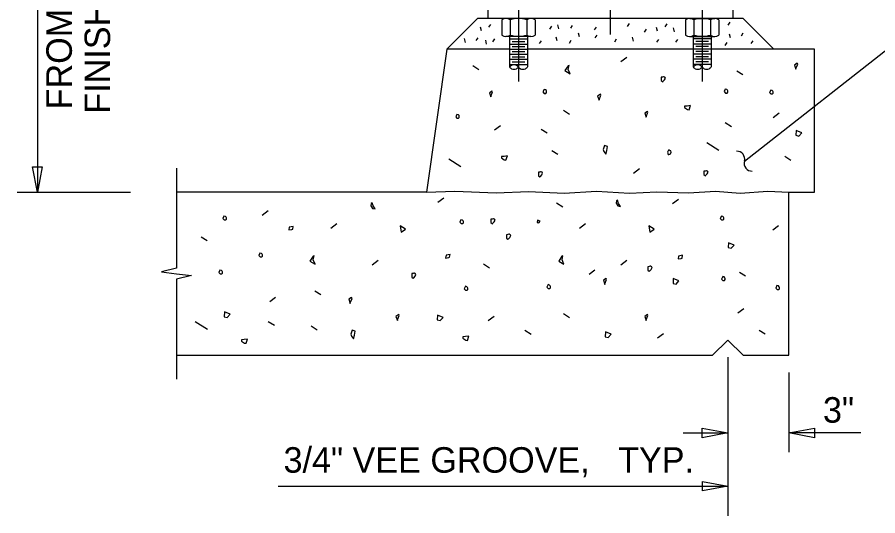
# Model space of a CAD drawing. Extents: x 0 to 22.7, y 0 to 15.7.
# Drawn here: x 16.522 to 20.034, y 3.448 to 5.483 of the extents above; entities that cross this region are included whole.
import ezdxf

# ---------------------------------------------------------------- set-up
doc = ezdxf.new("R2010")
doc.units = 0
for name, color, linetype in [('BRDG_ANNO_General-Notes', 7, 'Continuous'), ('BRDG_BASE_Dtlctrln', 7, 'Continuous'), ('BRDG_BASE_Obj-Line', 7, 'Continuous'), ('BRDG_BASE_Pattern', 7, 'Continuous'), ('BRDG_BASE_Phtline', 7, 'Continuous'), ('Default', 7, 'Continuous')]:
    doc.layers.add(name, color=color, linetype=linetype)

# ---------------------------------------------------------------- blocks, each defined once
blk = doc.blocks.new('TERM')
at = {"layer": 'Default'}
for p, q in [((-1.6, -0.267), (-1.6, 0.267)), ((-1.6, 0.267), (0, 0)), ((0, 0), (-1.6, -0.267))]:
    blk.add_line(p, q, dxfattribs=at)

msp = doc.modelspace()

# ---------------------------------------------------------------- linework, layer by layer
at = {"layer": 'BRDG_ANNO_General-Notes'}
for p, q in [((16.6043, 6.5193), (16.6043, 4.7693)), ((16.5849, 4.8726), (16.6236, 4.8726)), ((16.6043, 4.7693), (16.5849, 4.8726)), ((16.6236, 4.8726), (16.6043, 4.7693)), ((16.5219, 4.7693), (16.9841, 4.7693)), ((19.6716, 4.0332), (19.6716, 3.7074)), ((19.2393, 3.7856), (19.4216, 3.7856)), ((19.9648, 3.7856), (19.6716, 3.7856)), ((19.3182, 3.5489), (19.3182, 3.5877)), ((19.3182, 3.5877), (19.4216, 3.5683)), ((17.5869, 3.5683), (19.4216, 3.5683)), ((19.4216, 3.5683), (19.3182, 3.5489))]:
    msp.add_line(p, q, dxfattribs=at)
msp.add_lwpolyline([(19.4896, 4.8953), (20.1276, 5.3956), (20.5327, 5.3956)], dxfattribs=at)
for centre, start, end in [((19.4585, 4.9036), 344.9792, 91.2394), ((19.5208, 4.8869), 164.9792, 271.2394)]:
    msp.add_arc(centre, 0.0323, start, end, dxfattribs=at)
at = {"layer": 'BRDG_BASE_Dtlctrln'}
for p, q in [((18.9424, 7.3563), (18.9424, 5.4121)), ((18.5674, 5.7676), (18.5674, 5.2206)), ((19.3174, 5.7676), (19.3174, 5.2206)), ((19.4216, 4.0957), (19.4216, 3.4476))]:
    msp.add_line(p, q, dxfattribs=at)
at = {"layer": 'BRDG_BASE_Obj-Line'}
for p, q in [((18.4424, 5.5609), (18.4424, 5.4776)), ((19.4424, 5.5609), (19.4424, 5.4776)), ((18.2757, 5.3526), (18.4007, 5.4776)), ((19.4841, 5.4776), (18.4007, 5.4776)), ((18.4991, 5.4722), (18.4991, 5.4101)), ((18.5674, 5.4776), (18.5166, 5.4776)), ((18.5332, 5.4722), (18.5332, 5.4101)), ((18.6183, 5.4776), (18.5674, 5.4776)), ((18.6016, 5.4722), (18.6016, 5.4101)), ((18.6358, 5.4722), (18.6358, 5.4101)), ((19.2491, 5.4722), (19.2491, 5.4101)), ((19.2666, 5.4776), (19.3174, 5.4776)), ((19.2832, 5.4722), (19.2832, 5.4101)), ((19.3174, 5.4776), (19.3683, 5.4776)), ((19.3516, 5.4722), (19.3516, 5.4101)), ((19.3858, 5.4722), (19.3858, 5.4101)), ((19.6091, 5.3526), (19.4841, 5.4776)), ((18.5674, 5.4047), (18.5166, 5.4047)), ((18.5309, 5.4047), (18.5309, 5.2797)), ((18.5309, 5.3943), (18.6039, 5.3943)), ((18.5309, 5.3734), (18.6039, 5.3734)), ((18.5414, 5.3839), (18.5934, 5.3839)), ((18.6183, 5.4047), (18.5674, 5.4047)), ((18.6039, 5.4047), (18.6039, 5.2797)), ((19.2666, 5.4047), (19.3174, 5.4047)), ((19.2809, 5.4047), (19.2809, 5.2797)), ((19.3539, 5.3943), (19.2809, 5.3943)), ((19.3539, 5.3734), (19.2809, 5.3734)), ((19.3434, 5.4047), (19.2914, 5.4047)), ((19.3434, 5.3839), (19.2914, 5.3839)), ((19.3174, 5.4047), (19.3683, 5.4047)), ((19.3539, 5.4047), (19.3539, 5.2797)), ((18.2757, 5.3526), (18.1924, 4.7693)), ((18.5309, 5.3526), (18.2757, 5.3526)), ((18.5309, 5.3526), (18.6039, 5.3526)), ((18.5414, 5.363), (18.5934, 5.363)), ((18.5414, 5.3422), (18.5934, 5.3422)), ((19.2809, 5.3526), (18.6039, 5.3526)), ((19.3539, 5.3526), (19.2809, 5.3526)), ((19.3434, 5.363), (19.2914, 5.363)), ((19.3434, 5.3422), (19.2914, 5.3422)), ((19.7757, 5.3526), (19.3539, 5.3526)), ((19.7757, 4.7693), (19.7757, 5.3526)), ((18.5309, 5.3318), (18.6039, 5.3318)), ((18.5309, 5.3109), (18.6039, 5.3109)), ((18.5414, 5.3214), (18.5934, 5.3214)), ((19.3539, 5.3318), (19.2809, 5.3318)), ((19.3539, 5.3109), (19.2809, 5.3109)), ((19.3434, 5.3214), (19.2914, 5.3214)), ((18.5309, 5.2901), (18.6039, 5.2901)), ((18.5414, 5.3005), (18.5934, 5.3005)), ((19.3539, 5.2901), (19.2809, 5.2901)), ((19.3434, 5.3005), (19.2914, 5.3005)), ((18.1924, 4.7693), (17.1716, 4.7693)), ((19.6716, 4.1026), (19.6716, 4.7693)), ((19.6716, 4.7693), (19.7757, 4.7693)), ((19.4216, 4.1651), (19.3591, 4.1026)), ((19.4216, 4.1651), (19.4841, 4.1026)), ((17.1716, 4.1026), (19.3591, 4.1026)), ((19.4841, 4.1026), (19.6716, 4.1026))]:
    msp.add_line(p, q, dxfattribs=at)
for points in [[(17.1716, 4.8665), (17.1716, 4.459), (17.1101, 4.4436), (17.1716, 4.4359), (17.2331, 4.4282), (17.1716, 4.4129), (17.1716, 4.0054)], [(18.1924, 4.7693), (18.3085, 4.7726), (18.4759, 4.7658), (18.6081, 4.7713), (18.7539, 4.7651), (18.8861, 4.7732), (19.0211, 4.7651), (19.1318, 4.7705), (19.2614, 4.7665), (19.372, 4.7726), (19.4719, 4.7645), (19.5853, 4.7726), (19.6716, 4.7693)]]:
    msp.add_lwpolyline(points, dxfattribs=at)
for centre, radius, start, end in [((18.5161, 5.448), 0.0296, 54.7697, 125.2303), ((18.5674, 5.3672), 0.1104, 71.9685, 108.0315), ((18.6187, 5.448), 0.0296, 54.7697, 125.2303), ((19.2661, 5.448), 0.0296, 54.7697, 125.2303), ((19.3174, 5.3672), 0.1104, 71.9685, 108.0316), ((19.3687, 5.448), 0.0296, 54.7697, 125.2303), ((18.5161, 5.4343), 0.0296, 234.7697, 305.2303), ((18.5674, 5.5151), 0.1104, 251.9685, 288.0316), ((18.6187, 5.4343), 0.0296, 234.7697, 305.2303), ((19.2661, 5.4343), 0.0296, 234.7697, 305.2303), ((19.3174, 5.5151), 0.1104, 251.9684, 288.0315), ((19.3687, 5.4343), 0.0296, 234.7697, 305.2303), ((18.5492, 5.2658), 0.0228, 36.8699, 143.1301), ((18.5492, 5.2931), 0.0228, 216.8699, 323.1301), ((18.5856, 5.2931), 0.0228, 216.8699, 323.1301), ((19.2992, 5.2658), 0.0228, 36.8699, 143.1301), ((19.2992, 5.2931), 0.0228, 216.8699, 323.1301), ((19.3356, 5.2931), 0.0228, 216.8699, 323.1301)]:
    msp.add_arc(centre, radius, start, end, dxfattribs=at)
at = {"layer": 'BRDG_BASE_Pattern'}
for p, q in [((19.0098, 5.319), (18.9857, 5.3007)), ((18.3812, 5.2854), (18.4059, 5.2698)), ((19.4589, 5.2646), (19.4836, 5.249)), ((18.7517, 5.1027), (18.7764, 5.0871)), ((19.6311, 5.0908), (19.607, 5.0724)), ((18.494, 5.0396), (18.4699, 5.0213)), ((18.66, 5.026), (18.6848, 5.0104)), ((19.4117, 5.0526), (19.4365, 5.0369)), ((19.336, 4.9711), (19.3855, 4.9398)), ((18.7033, 4.939), (18.728, 4.9233)), ((18.2828, 4.9042), (18.3323, 4.8729)), ((19.6544, 4.9152), (19.6791, 4.8995)), ((19.0611, 4.8633), (19.037, 4.845)), ((17.1716, 4.7693), (17.1716, 4.7693)), ((18.2624, 4.7447), (18.2384, 4.7264)), ((18.7232, 4.7247), (18.748, 4.7091)), ((19.2203, 4.7387), (19.1962, 4.7204)), ((17.5454, 4.692), (17.5214, 4.6738)), ((17.8262, 4.639), (17.8021, 4.6207)), ((18.8412, 4.639), (18.8172, 4.6207)), ((19.6291, 4.6317), (19.6051, 4.6134)), ((17.2724, 4.5869), (17.2972, 4.5713)), ((17.9947, 4.4895), (17.9707, 4.4712)), ((18.425, 4.4759), (18.4497, 4.4603)), ((19.0098, 4.4895), (18.9857, 4.4712)), ((18.8797, 4.4508), (18.8556, 4.4325)), ((19.4695, 4.4427), (19.4943, 4.4271)), ((17.7366, 4.3662), (17.7613, 4.3507)), ((17.5765, 4.3393), (17.5524, 4.321)), ((19.4871, 4.2929), (19.4631, 4.2746)), ((18.4685, 4.2612), (18.4445, 4.243)), ((18.7517, 4.2732), (18.7764, 4.2577)), ((17.2488, 4.2412), (17.2983, 4.2099)), ((17.5466, 4.2411), (17.5714, 4.2255)), ((17.7215, 4.2224), (17.7461, 4.2067)), ((18.5941, 4.2048), (18.6189, 4.1892)), ((19.1594, 4.191), (19.1354, 4.1728)), ((19.5497, 4.2059), (19.5745, 4.1903))]:
    msp.add_line(p, q, dxfattribs=at)
for points in [[(18.7698, 5.284), (18.757, 5.2647), (18.7786, 5.2517), (18.7707, 5.2692), (18.7741, 5.2853)], [(19.694, 5.2876), (19.6997, 5.271), (19.6997, 5.2728), (19.707, 5.2913), (19.7052, 5.2949)], [(19.1502, 5.2378), (19.1502, 5.2238), (19.1565, 5.2193), (19.1584, 5.2211), (19.1639, 5.2267), (19.1675, 5.2341), (19.1648, 5.2378), (19.1611, 5.2395), (19.1594, 5.2395), (19.1557, 5.2385)], [(18.449, 5.1743), (18.4547, 5.1577), (18.4547, 5.1594), (18.462, 5.178), (18.4602, 5.1816)], [(18.6722, 5.1877), (18.6676, 5.1776), (18.673, 5.172), (18.6796, 5.172), (18.6823, 5.1749), (18.6823, 5.1803), (18.6814, 5.183), (18.6785, 5.1859)], [(18.8907, 5.1608), (18.8964, 5.1442), (18.8964, 5.146), (18.9037, 5.1645), (18.9018, 5.1682)], [(19.4117, 5.1892), (19.407, 5.179), (19.4124, 5.1734), (19.4191, 5.1734), (19.4218, 5.1764), (19.4218, 5.1817), (19.4208, 5.1844), (19.418, 5.1873)], [(19.597, 5.1856), (19.5924, 5.1755), (19.5978, 5.1698), (19.6044, 5.1698), (19.6071, 5.1728), (19.6071, 5.1782), (19.6062, 5.1808), (19.6033, 5.1838)], [(19.0827, 5.0912), (19.0884, 5.0746), (19.0884, 5.0764), (19.0957, 5.0949), (19.0939, 5.0986)], [(19.2564, 5.1203), (19.2453, 5.1194), (19.2453, 5.1139), (19.2573, 5.1056), (19.2638, 5.1047), (19.2703, 5.1222)], [(18.3159, 5.0862), (18.3113, 5.0761), (18.3167, 5.0705), (18.3233, 5.0705), (18.326, 5.0734), (18.326, 5.0788), (18.3252, 5.0815), (18.3222, 5.0844)], [(19.701, 5.0205), (19.7001, 5.0007), (19.7121, 4.9979), (19.7235, 5.0113)], [(18.919, 4.9597), (18.9134, 4.9432), (18.9163, 4.9348), (18.9245, 4.9238), (18.9282, 4.9385), (18.931, 4.9552)], [(19.176, 4.9314), (19.1789, 4.9221), (19.1816, 4.9221), (19.1854, 4.9231), (19.1881, 4.9257), (19.1907, 4.9314), (19.1899, 4.9368), (19.1854, 4.9378), (19.1834, 4.9397), (19.1797, 4.9397)], [(18.5087, 4.9147), (18.4977, 4.9137), (18.4977, 4.9082), (18.5096, 4.9), (18.5161, 4.8991), (18.5226, 4.9166)], [(18.6489, 4.8498), (18.6489, 4.8359), (18.6552, 4.8314), (18.6572, 4.8332), (18.6626, 4.8388), (18.6662, 4.8462), (18.6636, 4.8498), (18.6599, 4.8516), (18.6581, 4.8516), (18.6545, 4.8506)], [(19.3241, 4.8541), (19.3241, 4.8402), (19.3304, 4.8357), (19.3323, 4.8375), (19.3378, 4.8431), (19.3414, 4.8505), (19.3388, 4.8541), (19.3351, 4.8559), (19.3333, 4.8559), (19.3296, 4.8549)], [(17.9671, 4.7229), (17.965, 4.7126), (17.9719, 4.7024), (17.9834, 4.7002), (17.9742, 4.7123), (17.9703, 4.725)], [(18.968, 4.7335), (18.966, 4.7232), (18.9729, 4.713), (18.9844, 4.7107), (18.9752, 4.7229), (18.9712, 4.7356)], [(17.3654, 4.671), (17.3608, 4.6609), (17.3662, 4.6553), (17.3728, 4.6553), (17.3755, 4.6582), (17.3755, 4.6636), (17.3746, 4.6663), (17.3717, 4.6692)], [(18.3325, 4.6562), (18.3279, 4.6461), (18.3333, 4.6405), (18.3399, 4.6405), (18.3426, 4.6435), (18.3426, 4.6489), (18.3417, 4.6516), (18.3389, 4.6545)], [(18.4553, 4.6582), (18.4553, 4.6443), (18.4616, 4.6398), (18.4636, 4.6416), (18.469, 4.6472), (18.4727, 4.6546), (18.47, 4.6582), (18.4663, 4.66), (18.4645, 4.66), (18.4609, 4.659)], [(18.6447, 4.6544), (18.6443, 4.6445), (18.6503, 4.6431), (18.656, 4.6498)], [(19.3955, 4.671), (19.3909, 4.6609), (19.3963, 4.6553), (19.4029, 4.6553), (19.4056, 4.6582), (19.4056, 4.6636), (19.4047, 4.6663), (19.4018, 4.6692)], [(17.6317, 4.6254), (17.6298, 4.6144), (17.6428, 4.6162), (17.6464, 4.6181), (17.6483, 4.6291)], [(18.0845, 4.6317), (18.0883, 4.6059), (18.1068, 4.617)], [(19.0996, 4.6317), (19.1033, 4.6059), (19.1218, 4.617)], [(18.5185, 4.5949), (18.5185, 4.581), (18.5248, 4.5765), (18.5268, 4.5783), (18.5322, 4.5839), (18.5359, 4.5913), (18.5332, 4.5949), (18.5295, 4.5967), (18.5278, 4.5967), (18.5241, 4.5957)], [(19.4246, 4.5621), (19.4237, 4.5423), (19.4357, 4.5395), (19.4472, 4.5529)], [(17.5123, 4.5202), (17.5077, 4.5101), (17.5131, 4.5045), (17.5197, 4.5045), (17.5224, 4.5074), (17.5224, 4.5128), (17.5216, 4.5155), (17.5186, 4.5184)], [(17.7295, 4.5068), (17.7166, 4.4876), (17.7383, 4.4746), (17.7304, 4.4921), (17.7337, 4.5082)], [(18.272, 4.5109), (18.2701, 4.4999), (18.283, 4.5018), (18.2867, 4.5036), (18.2885, 4.5146)], [(18.7445, 4.5068), (18.7317, 4.4876), (18.7533, 4.4746), (18.7455, 4.4921), (18.7488, 4.5082)], [(19.2206, 4.5072), (19.2188, 4.4962), (19.2317, 4.4981), (19.2353, 4.4999), (19.2372, 4.5109)], [(19.0953, 4.4644), (19.0953, 4.4504), (19.1016, 4.4459), (19.1036, 4.4478), (19.109, 4.4533), (19.1127, 4.4607), (19.11, 4.4644), (19.1063, 4.4661), (19.1045, 4.4661), (19.1009, 4.4652)], [(17.3492, 4.4507), (17.3445, 4.4406), (17.3499, 4.4349), (17.3566, 4.4349), (17.3593, 4.4379), (17.3593, 4.4433), (17.3583, 4.4459), (17.3555, 4.4489)], [(18.1318, 4.4362), (18.1318, 4.4222), (18.1382, 4.4178), (18.1401, 4.4196), (18.1455, 4.4252), (18.1492, 4.4326), (18.1465, 4.4362), (18.1428, 4.438), (18.141, 4.438), (18.1374, 4.437)], [(18.6882, 4.3911), (18.6835, 4.381), (18.689, 4.3754), (18.6956, 4.3754), (18.6983, 4.3784), (18.6983, 4.3838), (18.6973, 4.3865), (18.6945, 4.3894)], [(18.9141, 4.4089), (18.9198, 4.3922), (18.9198, 4.3941), (18.9271, 4.4126), (18.9253, 4.4162)], [(19.1994, 4.4157), (19.1985, 4.3959), (19.2105, 4.3932), (19.222, 4.4066)], [(19.4012, 4.4243), (19.3966, 4.4141), (19.402, 4.4085), (19.4086, 4.4085), (19.4113, 4.4115), (19.4113, 4.4168), (19.4104, 4.4195), (19.4076, 4.4224)], [(18.3509, 4.3843), (18.3463, 4.3742), (18.3517, 4.3685), (18.3583, 4.3685), (18.361, 4.3715), (18.361, 4.3769), (18.3602, 4.3795), (18.3572, 4.3825)], [(19.6221, 4.3874), (19.6174, 4.3773), (19.6229, 4.3717), (19.6295, 4.3717), (19.6322, 4.3747), (19.6322, 4.3801), (19.6313, 4.3828), (19.6284, 4.3857)], [(17.8756, 4.3314), (17.8813, 4.3147), (17.8813, 4.3166), (17.8887, 4.3351), (17.8868, 4.3387)], [(17.368, 4.28), (17.3671, 4.2602), (17.3791, 4.2574), (17.3905, 4.2708)], [(18.0677, 4.2617), (18.0733, 4.2452), (18.0733, 4.2469), (18.0807, 4.2655), (18.0788, 4.2691)], [(18.237, 4.2667), (18.2361, 4.2469), (18.2481, 4.2442), (18.2596, 4.2576)], [(19.0827, 4.2617), (19.0884, 4.2452), (19.0884, 4.2469), (19.0957, 4.2655), (19.0939, 4.2691)], [(17.8892, 4.2055), (17.8836, 4.189), (17.8864, 4.1807), (17.8947, 4.1696), (17.8984, 4.1844), (17.9011, 4.2009)], [(18.3515, 4.1792), (18.3404, 4.1782), (18.3404, 4.1727), (18.3524, 4.1644), (18.3589, 4.1635), (18.3653, 4.181)], [(18.9229, 4.1982), (18.922, 4.1784), (18.934, 4.1756), (18.9455, 4.189)], [(17.4482, 4.1673), (17.4372, 4.1664), (17.4372, 4.1608), (17.4492, 4.1526), (17.4557, 4.1516), (17.4621, 4.1691)]]:
    msp.add_lwpolyline(points, close=True, dxfattribs=at)
at = {"layer": 'BRDG_BASE_Phtline'}
for p, q in [((18.4109, 5.4442), (18.4148, 5.4286)), ((18.4467, 5.4415), (18.4546, 5.4532)), ((18.6962, 5.4343), (18.7041, 5.446)), ((18.7269, 5.4514), (18.7308, 5.4358)), ((18.7807, 5.4379), (18.7885, 5.4496)), ((19.0123, 5.4451), (19.0202, 5.4568)), ((19.1667, 5.4433), (19.1745, 5.4551)), ((19.4234, 5.4505), (19.4313, 5.4622)), ((18.8113, 5.4191), (18.8153, 5.4034)), ((18.8776, 5.4307), (18.8855, 5.4424)), ((18.8812, 5.3983), (18.8891, 5.4101)), ((19.0823, 5.4217), (19.0902, 5.4335)), ((19.1291, 5.4424), (19.133, 5.4268)), ((19.1991, 5.4389), (19.2031, 5.4232)), ((19.4271, 5.4155), (19.4311, 5.3998)), ((19.4773, 5.4073), (19.4852, 5.4191)), ((18.3462, 5.3957), (18.3502, 5.3801)), ((18.3946, 5.3876), (18.4025, 5.3993)), ((18.4324, 5.3885), (18.4364, 5.3729)), ((18.4629, 5.3822), (18.4707, 5.394)), ((18.6532, 5.375), (18.661, 5.3868)), ((18.7197, 5.4029), (18.7236, 5.3873)), ((18.7753, 5.3768), (18.7831, 5.3885)), ((18.9602, 5.3822), (18.9681, 5.394)), ((19.0321, 5.4011), (19.0361, 5.3855)), ((19.1326, 5.3804), (19.1404, 5.3921)), ((19.2098, 5.3804), (19.2177, 5.3921)), ((19.4109, 5.3678), (19.4187, 5.3796)), ((19.5168, 5.375), (19.5247, 5.3868))]:
    msp.add_line(p, q, dxfattribs=at)

# ---------------------------------------------------------------- block references
at = {"layer": 'BRDG_ANNO_General-Notes', "xscale": 0.06510416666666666, "yscale": 0.0732421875}
msp.add_blockref('TERM', (19.4216, 3.7856), dxfattribs=at)
at = {"layer": 'BRDG_ANNO_General-Notes', "xscale": 0.06510416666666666, "yscale": 0.0732421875, "rotation": 180}
msp.add_blockref('TERM', (19.6716, 3.7856), dxfattribs=at)

# ---------------------------------------------------------------- texts
at = {"layer": 'BRDG_ANNO_General-Notes'}
for s, p in [('FROM TOP OF', (16.7449, 5.1068)), ('FINISH GRADE', (16.9011, 5.0891))]:
    msp.add_text(s, height=0.104167, rotation=90, dxfattribs=at).set_placement(p)
for s, height, p in [('3"', 0.10417, (19.8102, 3.8277)), ('3/4" VEE GROOVE,   TYP.', 0.104167, (17.6088, 3.6235))]:
    msp.add_text(s, height=height, dxfattribs=at).set_placement(p)

doc.saveas('drawing.dxf')
